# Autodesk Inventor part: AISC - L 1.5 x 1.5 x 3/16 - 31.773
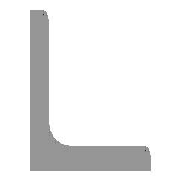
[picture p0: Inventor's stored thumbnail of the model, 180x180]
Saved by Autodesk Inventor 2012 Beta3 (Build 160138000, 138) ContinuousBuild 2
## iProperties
IsCustomPart: 1
Created: 2010-11
Part Number: AISC - L 1.5 x 1.5 x 3/16 - 31.773
Material: Steel, Mild
Description: Angle Steel
Document SubType Name: Modeling
Standard: ANSI
Designer: Beta-8540w
Standards Organization: ANSI
Language: en-US
Size Designation: L 1.5 x 1.5 x 3/16
Categories: <MemberInstance><Categories><Category DisplayName="Structural Shapes" InternalName="089c4875-fa83-4c05-b084-43b9cc11f5ed" Mnemonic="GRDR"><CategoryParameter Dis
Stock Number: L 1.5 x 1.5 x 3/16
Density: 7.86 g/cm^3
G_L: 31.773 in
G_W: 1.500 in
G_H: 1.500 in
+AB804AD9-6BA4-4EFD-9C9E-0920120F2FE1+CUTDETAIL1: Cut
_CCFamilyMember: 5
_CCFamilyDisplayName: ANSI L (Equal angles) - Angle Steel
_FrameMemberDoc: Frame Member File
_Version: 15.0.0
_GetPNFromCC: 1
Author: Beta-8540w
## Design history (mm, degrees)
node "Start plane"
node "End plane"
sketch "Sketch"
  geometry: L1 (38.1, 0)-(0, 0); L2 (0, 0)-(0, 38.1); L3 (0, 38.1)-(2.476, 38.1); L4 (4.762, 35.814)-(4.762, 9.589); L5 (9.588, 4.763)-(35.814, 4.763); L6 (38.1, 2.477)-(38.1, 0); L7 (0, -11.041)-(0, 31.538); L8 (-11.041, 0)-(31.538, 0); L9 (0, 48.496)-(0, -20.964) reference; L10 (-20.964, 0)-(48.496, 0) reference; A1 r 4.826 centre (9.588, 9.589) between (4.762, 9.589) and (9.588, 4.763); A2 r 2.286 centre (2.476, 35.814) between (4.762, 35.814) and (2.476, 38.1); A3 r 2.286 centre (35.814, 2.477) between (38.1, 2.477) and (35.814, 4.763); 3 further points
  constraints: 16 end point, 6 point on circle, 6 point on line, 6 tangent, 4 parallel, 3 centre point, 2 collinear, 1 equal radius, 1 horizontal, 1 perpendicular
  dimensions: "d0" = 38.1 distance between parallel lines of L6 L2 (= G_H); "d1" = 38.1 distance between parallel lines of L3 L1 (= G_H); "d2" = 4.7625 distance between parallel lines of L2 L4 (= G_T); "d3" = 4.7625 distance between parallel lines of L1 L5 (= G_T); "d10" = 0 distance between parallel lines of L7 L2 (computed from ex); "d11" = 0 distance between parallel lines of L8 L1 (computed from d10); "d14" = 4.826 radius of A1 (= G_IR); "d15" = 2.286 radius of A2 (= G_ER)
extrude "Body" new body sketch "Sketch" stored distance "d4" = 807.0404 (= G_L); taper "d5" = 0 deg
node "Driven Length"
  sketch "Sketch3"
    geometry: L1 (0, 0)-(10, 0) reference
    constraints: 2 end point, 1 horizontal
  workplane "Work Plane3"
  sketch "Sketch4"
    geometry: L1 (-2, 0)-(12, 0) reference; L2 (-2, 807.04)-(12, 807.04) reference
    dimensions: "d17" = 807.0404 distance between parallel lines of L1 L2 (derived)
workplane "Work Plane4"
split "Split1"
body "Solid1"
other parameters: "G_H" = 38.1 [user parameter; used in 2 equation terms], "G_T" = 4.7625 [user parameter; used in 2 equation terms], "G_ER" = 2.286 [user parameter; used in 1 equation term], "G_IR" = 4.826 [user parameter; used in 1 equation term], "G_L" = 807.0404 (= d17) [user parameter; used in 1 equation term], "ex" = 0 [user parameter; used in 1 equation term], "G_OFFSET_START" = 0 [user parameter; used in 1 equation term], "G_OFFSET_END" = -29.72503 [user parameter; used in 1 equation term], "d12" = 0 (computed from G_OFFSET_START), "d13" = 807.0404 (= G_OFFSET_END + B_L), "B_L" = 836.76542 [user parameter; used in 1 equation term], "d16" = 90 deg, "MAS" = 0.26787 [user parameter]
